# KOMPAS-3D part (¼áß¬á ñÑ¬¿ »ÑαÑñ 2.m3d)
File: created 06.04.2016 12:01:11, last saved 22.07.2016 16:02:09.
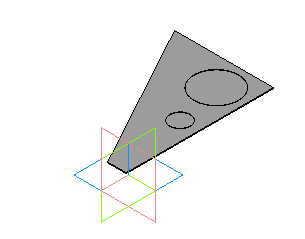
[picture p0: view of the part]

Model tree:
1. Эскиз:1
2. Операция выдавливания:1
     Толщина стенки 2 = 15; Расстояние 1 = 0.8; Расстояние 2 = 96.2519
3. Эскиз:2
4. Вырезать элемент выдавливания:1
     Толщина стенки 1 = 2; Толщина стенки 2 = 2; Расстояние 1 = 10
5. Эскиз:3
6. Вырезать элемент выдавливания:2
     Толщина стенки 1 = 2; Толщина стенки 2 = 2; Расстояние 1 = 10
7. Эскиз:4
8. Вырезать элемент выдавливания:3
     Толщина стенки 1 = 2; Толщина стенки 2 = 2; Расстояние 1 = 10
9. Эскиз:5
10. Вырезать элемент выдавливания:4
     Толщина стенки 1 = 2; Толщина стенки 2 = 2; Расстояние 1 = 0.4
11. Эскиз:6
12. Вырезать элемент выдавливания:5
     Толщина стенки 1 = 2; Толщина стенки 2 = 2; Расстояние 1 = 0.4
13. Эскиз:7
14. Вырезать элемент выдавливания:6
     Толщина стенки 1 = 2; Толщина стенки 2 = 2; Расстояние 1 = 10.4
